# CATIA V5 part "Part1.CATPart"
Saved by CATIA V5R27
Part number: Part1
Material "Alominium": density 2433.33 kg/m3
Bounding box of the stored display mesh (mm): x -19 to 19, y 0 to 3, z 0 to 300
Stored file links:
  E:\university\my-thesis\My Thesis Publication\Final-Updata\CAD\Part1.CATPart
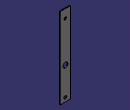
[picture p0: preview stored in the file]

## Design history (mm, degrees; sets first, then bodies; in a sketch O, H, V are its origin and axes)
Body1 (main body)
  Sketch1 on zx-plane, origin (0, 0, 0), H (-1, 0, 0), V (0, 0, 1)
    point P1 (19, 0)
    line L1 (19, 0) -> (-19, 0)
    line L2 (-19, 0) -> (-19, 300)
    line L3 (19, 300) -> (19, 0)
    line L4 (19, 300) -> (-19, 300)
    circle A1 centre (0, 15) radius 6
    point P5 (0, 15)
    point P6 (0, 21)
    circle A2 centre (0, 118.5) radius 9.5
    point P7 (0, 118.5)
    circle A3 centre (0, 268.5) radius 5
    point P8 (0, 268.5)
    length L1 = 38
    length L3 = 300
    radius A1 = 6
    distance P5 L1 = 15
    distance L1 P7 = 118.5
    radius A2 = 9.5
    radius A3 = 5
    distance P8 L4 = 31.5
    coincidence: P1 H, P5 V, A1 P6, P6 V, P7 V, P8 V
    horizontal: L1 H, L4 H
    vertical: L2 V, L3 V
    symmetry: L2 L3 V
  Pad1: profile Sketch1, direction (0, 1, 0), length 3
